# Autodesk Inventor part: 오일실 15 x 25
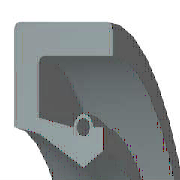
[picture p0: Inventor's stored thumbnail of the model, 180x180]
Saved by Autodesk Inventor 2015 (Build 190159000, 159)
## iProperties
IsCustomPart: 0
Created: 2015-10
Part Number: 오일실 15 x 25
Material: Rubber
Description: 오일-실
Document SubType Name: Modeling
Standard: KS B 2804
Designer: mdu
Standards Organization: KS
Language: ko-KR
Size Designation: S - 15 25 7
Categories: <MemberInstance><Categories><Category DisplayName="샤프트 부품" InternalName="7f7aeb1f-a693-4053-b835-cee3144e0d98" Mnemonic="SHFT"><Category DisplayName="실링" Intern
Density: 0.93 g/cm^3
Appearance: Rubber - Black - Version 1.1
Author: mdu
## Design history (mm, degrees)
revolve "본체" stored, may be unused: angle "d17" = 90 deg
revolve "스프링1" stored, may be unused: angle "d18" = 90 deg
body "Solid1"
sketch "스케치1"
  geometry: L1 (0, 12.5)-(7, 12.5); L2 (7, 12.5)-(7, 11.25); L3 (7, 11.25)-(1.75, 11.25); L4 (0, 12.5)-(0, 9.6); L5 (0, 9.6)-(1.75, 9.25); L6 (1.75, 9.25)-(4.9, 7.5); L7 (4.9, 7.5)-(0, 7.5); L8 (6.3, 8.375)-(6.3, 9.6); L9 (0, 0)-(9.586, 0) reference; L10 (4.9, 7.5)-(6.3, 8.375); L11 (0, 18)-(0, -3) reference; L12 (-1.917, 0)-(11.503, 0) reference; L13 (4.2, 9.6)-(1.75, 10.09); L14 (1.75, 10.09)-(1.75, 11.25); L15 (6.3, 9.6)-(5.6, 9.6); C1 r 0.455 at (4.9, 9.6); A1 r 0.7 centre (4.9, 9.6) between (5.6, 9.6) and (4.2, 9.6)
  constraints: 26 end point, 5 horizontal alignment, 4 perpendicular, 2 centre point, 2 collinear, 2 horizontal, 2 parallel, 2 point on circle, 2 point on line, 2 vertical alignment, 1 coincident
  dimensions: "d0" = 25 diameter of L1 L9 (= SD2); "d1" = 16.75 diameter of L8.start L9 (= ABDM); "d2" = 1.25 distance of L1.end L2.end (computed from SD); "d3" = 0.91 diameter of C1 (= SPDI); "d4" = 1.4 diameter of A1 (= SPDA); "d5" = 15 diameter of L6.end L9 (= NND); "d6" = 18.5 diameter of L5.end L9 (= TKDM); "d7" = 19.2 diameter of L4.end L9 (= HLDM); "d8" = 4.9 distance from line of C1.centre L4 (= SPDST); "d9" = 6.3 distance between parallel lines of L8 L4 (= SDI); "d10" = 7 distance between parallel lines of L2 L4 (= SWDT); "d12" = 1.75 distance between parallel lines of L14 L4 (= SD)
fillet "모깎기1" dims "d11" = 0.3 (= RR)
other parameters: "SD2" = 25 [user parameter; used in 1 equation term], "SWDT" = 7 [user parameter; used in 1 equation term], "RR" = 0.3 [user parameter; used in 1 equation term], "SD" = 1.75 [user parameter; used in 2 equation terms], "NND" = 15 [user parameter; used in 1 equation term], "SPDA" = 1.4 [user parameter; used in 1 equation term], "SPDI" = 0.91 [user parameter; used in 1 equation term], "TKDM" = 18.5 [user parameter; used in 1 equation term], "HLDM" = 19.2 [user parameter; used in 1 equation term], "ABDM" = 16.75 [user parameter; used in 1 equation term], "SDI" = 6.3 [user parameter; used in 1 equation term], "SPDST" = 4.9 [user parameter; used in 1 equation term], "d13" = 0, "d14" = 0, "d15" = 0, "LAB" = 0.35 [user parameter]
